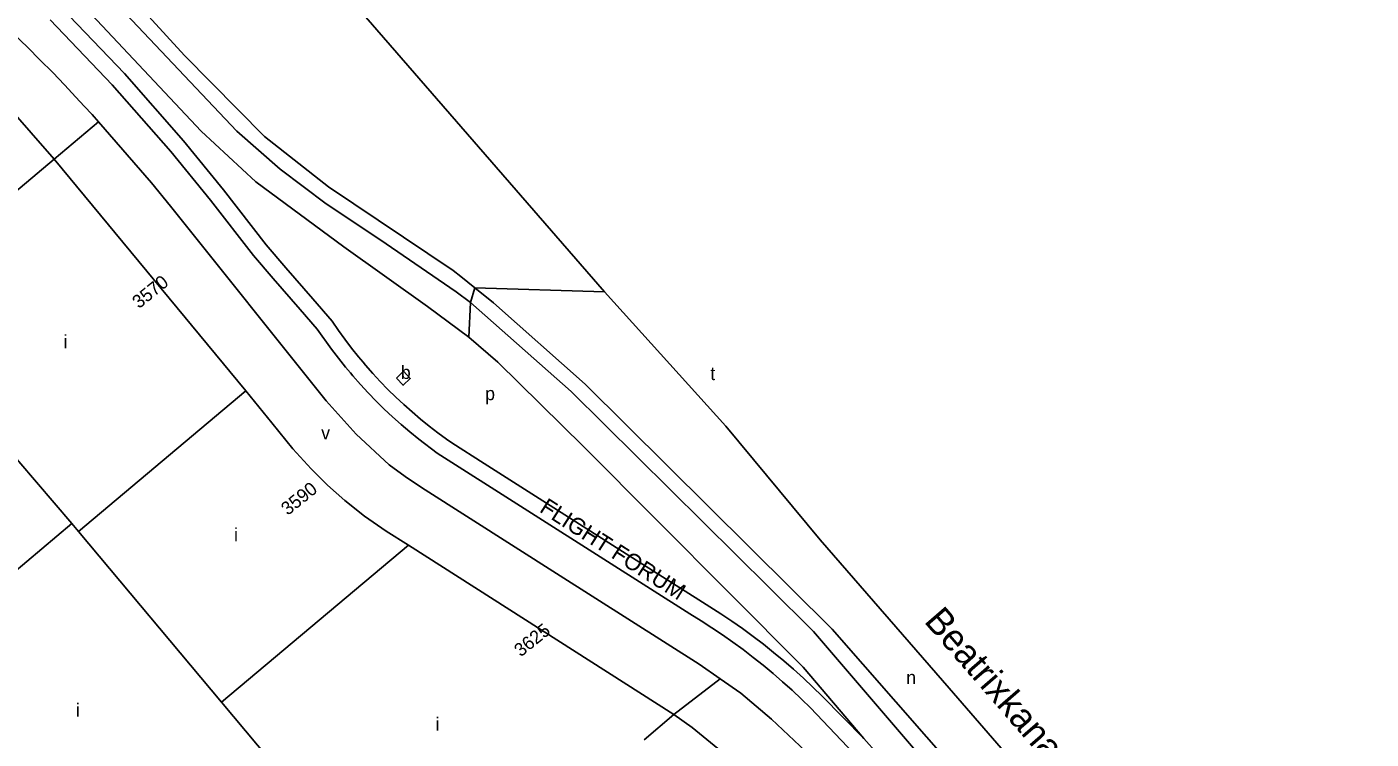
# Model space of a CAD drawing. Extents: x 154765 to 156627, y 383996 to 386132.
# Drawn here: x 156222.1 to 156627.3, y 384816.7 to 385031.4 of the extents above; entities that cross this region are included whole.
import ezdxf

# ---------------------------------------------------------------- set-up
doc = ezdxf.new("R2010")
doc.units = 0
for name, color, linetype in [('BLT_Basislijn', 7, 'Continuous'), ('BLT_Bebouwing', 7, 'Continuous'), ('BLT_Centroide', 7, 'Continuous'), ('BLT_Huisnummer', 7, 'Continuous'), ('BLT_Onderverdeling_panden', 7, 'Continuous'), ('BLT_Straatnaam', 7, 'Continuous'), ('BLT_Vlakafsluiter', 7, 'Continuous'), ('BLT_Waternaam_spoorwegen', 7, 'Continuous')]:
    doc.layers.add(name, color=color, linetype=linetype)

msp = doc.modelspace()

# ---------------------------------------------------------------- linework, layer by layer
at = {"layer": 'BLT_Basislijn'}
for p, q in [((156233.92, 385138.38), (156396.28, 384951.59)), ((156230.36, 384991.57), (156243.73, 385002.8)), ((156294.28, 384965.69), (156300.19, 384958.85)), ((156290.41, 384962.52), (156296.41, 384955.58)), ((156296.41, 384955.58), (156304.51, 384946.22)), ((156300.19, 384958.85), (156308.29, 384949.49)), ((156352.94, 384956.17), (156357.16, 384952.81)), ((156308.29, 384949.49), (156314.18, 384942.68)), ((156304.51, 384946.22), (156309.66, 384940.27)), ((156345.81, 384902.89), (156397.09, 384870.28)), ((156350.19, 384906.03), (156360.01, 384899.79)), ((156360.01, 384899.79), (156399.77, 384874.5)), ((156399.77, 384874.5), (156424.65, 384858.68)), ((156397.09, 384870.28), (156421.97, 384854.47)), ((156431.1, 384834.92), (156417.18, 384824.17)), ((156474.41, 384816.92), (156482.67, 384807.68))]:
    msp.add_line(p, q, dxfattribs=at)
for points in [[(156355.31, 384937.94), (156342.88, 384947.16), (156317.69, 384965.17), (156291.09, 384984.71), (156274.62, 384999.98), (156232.29, 385045.25), (156217.91, 385058.47), (156203.59, 385068.29), (156194.75, 385073.44), (156185.53, 385077.94), (156179.69, 385079.71)], [(156220.54, 385073.73), (156248.99, 385045.43), (156269.67, 385022.85), (156293.79, 384998.39), (156313.09, 384983.23), (156350.62, 384958.03), (156352.94, 384956.17)], [(156224.8, 385062.93), (156236.74, 385051.98), (156252.07, 385035.29), (156285.41, 384999.98), (156298.48, 384988.57), (156312.29, 384978.05), (156328.52, 384967.37), (156351.57, 384951.57)], [(156232.58, 385037.15), (156251.52, 385017.33), (156269.33, 384997.12), (156281.41, 384982.3), (156294.28, 384965.69)], [(156229.13, 385033.53), (156247.83, 385013.95), (156265.52, 384993.89), (156277.49, 384979.19), (156290.41, 384962.52)], [(156218.09, 385029.33), (156222.38, 385025.19), (156226.08, 385021.52), (156229.92, 385017.65), (156233.45, 385013.94), (156236.91, 385010.24), (156239.44, 385007.57), (156241.77, 385004.98), (156243.73, 385002.8)], [(156431.1, 384834.92), (156424.77, 384839.32), (156382.92, 384865.94), (156341.08, 384892.56), (156336.13, 384895.89), (156331.34, 384899.44), (156321.43, 384908.68), (156312.37, 384918.74), (156265.45, 384977.36), (156259.66, 384984.42), (156243.73, 385002.8)], [(156351.57, 384951.57), (156355.83, 384948.33)], [(156357.16, 384952.81), (156362.82, 384948.29), (156390.43, 384923.73), (156464.84, 384849.93), (156531.64, 384773.61), (156541.16, 384758.02), (156555.23, 384719.97), (156559.9, 384702.65), (156565.87, 384689.49), (156590.1, 384653.16)], [(156396.28, 384951.59), (156432.83, 384911.03), (156461.21, 384876.86)], [(156355.83, 384948.33), (156386.15, 384921.5), (156445.88, 384862.4)], [(156309.66, 384940.27), (156313.98, 384934.28), (156316.06, 384931.54), (156318.21, 384928.85), (156319.66, 384927.11)], [(156314.18, 384942.68), (156316.06, 384939.94), (156318, 384937.25), (156320.01, 384934.61), (156322.08, 384932.01), (156323.49, 384930.33)], [(156474.41, 384816.92), (156456.09, 384838.45), (156389.86, 384904.91), (156364.13, 384930.33), (156355.31, 384937.94)], [(156319.66, 384927.12), (156320.41, 384926.21), (156322.69, 384923.63), (156325.02, 384921.1), (156327.42, 384918.63), (156329.87, 384916.22), (156332.38, 384913.87), (156334.94, 384911.58), (156337.56, 384909.35), (156340.24, 384907.18), (156345.81, 384902.89)], [(156323.49, 384930.33), (156324.21, 384929.47), (156326.4, 384926.98), (156328.65, 384924.54), (156330.96, 384922.15), (156333.33, 384919.83), (156335.75, 384917.56), (156338.23, 384915.35), (156340.76, 384913.2), (156343.34, 384911.11), (156345.97, 384909.08), (156348.64, 384907.12), (156350.19, 384906.03)], [(156461.21, 384876.86), (156500.12, 384832.08), (156571.29, 384749.98), (156627.31, 384685.36)], [(156445.88, 384862.4), (156459.19, 384849.23), (156526.76, 384770.43)], [(156424.65, 384858.68), (156428.01, 384856.62), (156431.33, 384854.5), (156434.6, 384852.3), (156437.83, 384850.04), (156441.01, 384847.71), (156444.14, 384845.32), (156447.22, 384842.87), (156450.26, 384840.35), (156453.24, 384837.78), (156456.17, 384835.14), (156459.04, 384832.44), (156461.86, 384829.69), (156474.41, 384816.92)], [(156421.97, 384854.47), (156425.35, 384852.39), (156428.58, 384850.32), (156431.77, 384848.18), (156434.92, 384845.97), (156438.01, 384843.71), (156441.07, 384841.38), (156444.07, 384838.99), (156447.03, 384836.54), (156449.93, 384834.03), (156452.78, 384831.46), (156455.59, 384828.83), (156458.33, 384826.15), (156478.79, 384804.53)], [(156437.3, 384830.61), (156431.1, 384834.92)], [(156461.75, 384611.75), (156464.21, 384613.72), (156474.33, 384624.05), (156482.97, 384635.11), (156490.49, 384646.95), (156495.84, 384657.86), (156500.12, 384669.22), (156504.26, 384684.99), (156506.07, 384698.77), (156506.3, 384712.83), (156504.66, 384726.8), (156502.61, 384735.77), (156500.12, 384744.63), (156496.89, 384754.19), (156491.08, 384766.97), (156483.95, 384779.07), (156475.68, 384791.3), (156466.5, 384802.86), (156456.87, 384813.12), (156446.58, 384822.73), (156437.3, 384830.61)]]:
    msp.add_lwpolyline(points, dxfattribs=at)
at = {"layer": 'BLT_Bebouwing'}
for p, q in [((156230.36, 384991.57), (156288.15, 384921.74)), ((156214.39, 384906.69), (156235.7, 384881.73)), ((156337.12, 384875.19), (156417.18, 384824.17))]:
    msp.add_line(p, q, dxfattribs=at)
for points in [[(156230.36, 384991.57), (156216.44, 385007.43), (156213.23, 385010.86), (156209.65, 385014.4), (156205.77, 385018.02), (156202.32, 385014.64), (156196.34, 385021.8)], [(156288.15, 384921.74), (156296, 384912.04), (156302.33, 384904.21), (156307.77, 384898.19), (156312.7, 384893.33), (156318.01, 384888.63), (156323.93, 384883.96), (156330.46, 384879.42), (156337.12, 384875.19)], [(156439.52, 384806.36), (156438.71, 384807.08), (156422.69, 384820.28), (156417.18, 384824.17)]]:
    msp.add_lwpolyline(points, dxfattribs=at)
msp.add_lwpolyline([(156333.49, 384925.57), (156335.64, 384927.61), (156337.69, 384925.46), (156335.54, 384923.41)], close=True, dxfattribs=at)
at = {"layer": 'BLT_Onderverdeling_panden'}
for p, q in [((156179.32, 384948.68), (156230.36, 384991.57)), ((156235.7, 384881.73), (156184.26, 384838.5)), ((156237.7, 384879.35), (156280.84, 384827.93))]:
    msp.add_line(p, q, dxfattribs=at)
for points in [[(156237.7, 384879.35), (156288.15, 384921.74)], [(156237.7, 384879.35), (156235.7, 384881.73)], [(156337.12, 384875.19), (156280.84, 384827.93)], [(156280.84, 384827.93), (156295.22, 384810.59)], [(156417.18, 384824.17), (156408.15, 384816.57)]]:
    msp.add_lwpolyline(points, dxfattribs=at)
at = {"layer": 'BLT_Vlakafsluiter'}
for p, q in [((156357.16, 384952.81), (156355.83, 384948.33)), ((156357.16, 384952.81), (156396.28, 384951.59)), ((156355.83, 384948.33), (156355.31, 384937.94))]:
    msp.add_line(p, q, dxfattribs=at)

# ---------------------------------------------------------------- texts
at = {"layer": 'BLT_Centroide'}
for s, p in [('i', (156233.15, 384934.58)), ('b', (156334.84, 384925.3)), ('t', (156428.12, 384924.96)), ('p', (156360.25, 384918.91)), ('v', (156310.84, 384907.09)), ('i', (156284.57, 384876.36)), ('n', (156487.18, 384833.32)), ('i', (156236.89, 384823.53)), ('i', (156345.28, 384819.29))]:
    msp.add_text(s, height=4, dxfattribs=at).set_placement(p)
at = {"layer": 'BLT_Huisnummer'}
for s, p in [('3570', (156255.91, 384946.33)), ('3590', (156300.77, 384884)), ('3625', (156371.01, 384841.36))]:
    msp.add_text(s, height=4, rotation=38.8534, dxfattribs=at).set_placement(p)
at = {"layer": 'BLT_Straatnaam'}
msp.add_text('FLIGHT FORUM', height=5, rotation=327.3725, dxfattribs=at).set_placement((156376.35, 384885.44))
at = {"layer": 'BLT_Waternaam_spoorwegen'}
msp.add_text('Beatrixkanaal', height=7.9999, rotation=310.9054, dxfattribs=at).set_placement((156492.33, 384852.15))

doc.saveas('drawing.dxf')
